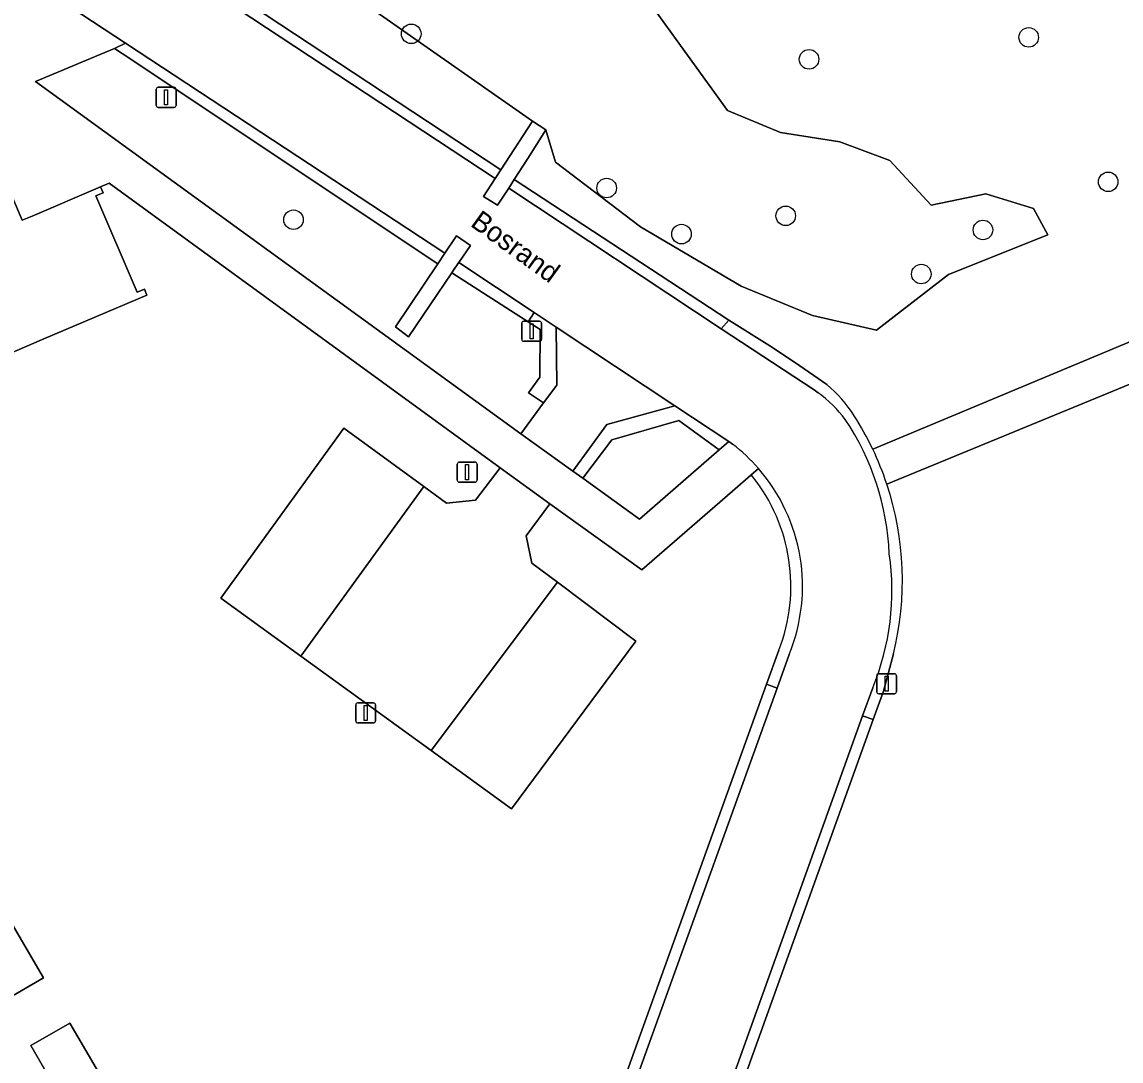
# Model space of a CAD drawing. Extents: x 156661 to 157576, y 383570 to 384425.
# Drawn here: x 156703.3 to 156758.2, y 383820 to 383871.9 of the extents above; entities that cross this region are included whole.
import ezdxf

# ---------------------------------------------------------------- set-up
doc = ezdxf.new("R2010")
doc.units = 0
for name, color, linetype in [('IMGEO_Boom', 7, 'Continuous'), ('IMGEO_Groenvoorziening', 7, 'Continuous'), ('IMGEO_Lichtmast', 7, 'Continuous'), ('IMGEO_Muur', 7, 'Continuous'), ('IMGEO_Openbare_ruimte_label', 7, 'Continuous'), ('IMGEO_Pand', 7, 'Continuous'), ('IMGEO_Parkeervlak_open', 7, 'Continuous'), ('IMGEO_Rijbaan_lokaal_gesloten', 7, 'Continuous'), ('IMGEO_Rijbaan_lokaal_halfverhard', 7, 'Continuous'), ('IMGEO_Rijbaan_lokaal_open', 7, 'Continuous'), ('IMGEO_Verkeersbordpaal', 7, 'Continuous'), ('IMGEO_Voetpad_halfverhard', 7, 'Continuous'), ('IMGEO_Voetpad_open', 7, 'Continuous')]:
    doc.layers.add(name, color=color, linetype=linetype)

msp = doc.modelspace()

# ---------------------------------------------------------------- linework, layer by layer
at = {"layer": 'IMGEO_Boom'}
for centre in [(156722.76, 383871.306), (156753.622, 383871.131), (156742.643, 383870.034), (156732.528, 383863.603), (156757.595, 383863.914), (156716.876, 383862.021), (156741.478, 383862.217), (156751.335, 383861.51), (156736.267, 383861.304), (156748.252, 383859.308)]:
    msp.add_circle(centre, 0.489, dxfattribs=at)
at = {"layer": 'IMGEO_Groenvoorziening'}
for points in [[(156716.183, 383876.493), (156711.792, 383874.695), (156713.985, 383873.248), (156727.234, 383864.506), (156728.814, 383866.945), (156719.836, 383873.239), (156729.567, 383879.935), (156725.091, 383891.83)], [(156729.567, 383879.935), (156738.568, 383867.47), (156741.218, 383866.376), (156744.176, 383865.917), (156746.68, 383864.987), (156748.744, 383862.749), (156751.487, 383863.31), (156753.862, 383862.586), (156754.58, 383861.26), (156749.606, 383859.293), (156746.013, 383856.5), (156742.821, 383857.242), (156739.254, 383858.704), (156734.225, 383861.669), (156729.97, 383864.893), (156729.492, 383866.507), (156728.58, 383865.086), (156727.906, 383864.035), (156738.637, 383857.007), (156740.683, 383855.728), (156741.967, 383854.876), (156743.528, 383853.784)], [(156739.821, 383849.196), (156739.736, 383849.264), (156738.813, 383848.462), (156734.285, 383844.531), (156729.684, 383847.837), (156728.506, 383846.223), (156728.792, 383844.873), (156730.073, 383843.909), (156733.979, 383840.969), (156727.773, 383832.588), (156723.749, 383835.507), (156717.245, 383840.225), (156713.248, 383843.125), (156719.396, 383851.612), (156723.39, 383848.696), (156724.521, 383847.87), (156725.971, 383848.018), (156727.201, 383849.634), (156707.654, 383863.85), (156707.237, 383863.666), (156707.363, 383863.372), (156706.995, 383863.214), (156709.056, 383858.397), (156709.424, 383858.554), (156709.549, 383858.26), (156704.398, 383856.067), (156692.389, 383850.886)], [(156745.823, 383850.568), (156763.462, 383857.925)], [(156764.227, 383856.088), (156746.53, 383848.809)], [(156740.523, 383838.828), (156741.132, 383840.518)], [(156746.863, 383840.339), (156746.357, 383838.464), (156745.849, 383837.052), (156732.467, 383799.845), (156731.117, 383796.092)], [(156725.657, 383797.552), (156727.175, 383801.768), (156740.523, 383838.828)], [(156696.966, 383836.824), (156704.38, 383824.151), (156702.342, 383822.975)]]:
    msp.add_lwpolyline(points, dxfattribs=at)
for points in [[(156738.568, 383867.47), (156729.567, 383879.935), (156719.836, 383873.239), (156728.814, 383866.945), (156729.492, 383866.507), (156729.97, 383864.893), (156734.225, 383861.669), (156739.254, 383858.704), (156742.821, 383857.242), (156746.013, 383856.5), (156749.606, 383859.293), (156754.58, 383861.26), (156753.862, 383862.586), (156751.487, 383863.31), (156748.744, 383862.749), (156746.68, 383864.987), (156744.176, 383865.917), (156741.218, 383866.376)], [(156708.317, 383870.317), (156707.93, 383870.575), (156707.439, 383870.369), (156703.983, 383868.92), (156728.241, 383851.334), (156729.371, 383852.868), (156728.621, 383853.376), (156729.181, 383854.15), (156729.2, 383856.537), (156728.602, 383856.921), (156724.79, 383859.373), (156722.627, 383856.175), (156721.975, 383856.663), (156724.088, 383859.825)], [(156738.154, 383850.528), (156736.128, 383851.996), (156732.78, 383851.024), (156731.338, 383849.106), (156734.161, 383847.065)], [(156696.966, 383836.824), (156695.097, 383835.702), (156699.159, 383829.422), (156702.342, 383822.975), (156704.38, 383824.151)], [(156705.701, 383821.894), (156703.75, 383820.772), (156715.859, 383799.798), (156781.035, 383689.82), (156782.468, 383690.79), (156717.547, 383800.885), (156717.868, 383801.092)], [(156782.468, 383690.79), (156781.035, 383689.82), (156715.859, 383799.798), (156703.75, 383820.772), (156705.701, 383821.894), (156717.868, 383801.092), (156717.547, 383800.885)]]:
    msp.add_lwpolyline(points, close=True, dxfattribs=at)
for centre, radius, start, end in [((156739.342, 383848.708), 6.579, 32.3261, 50.492), ((156731.863, 383843.898), 15.472, 25.5376, 32.5657), ((156732.931, 383843.717), 8.803, 338.6915, 38.4901), ((156732.053, 383843.998), 15.255, 346.1207, 18.3821)]:
    msp.add_arc(centre, radius, start, end, dxfattribs=at)
at = {"layer": 'IMGEO_Lichtmast'}
for p, q in [((156710.015, 383867.735), (156710.015, 383868.535)), ((156710.015, 383868.535), (156710.015, 383867.735)), ((156710.115, 383868.635), (156710.905, 383868.635)), ((156710.905, 383868.635), (156710.115, 383868.635)), ((156711.005, 383868.535), (156711.005, 383867.735)), ((156711.005, 383867.735), (156711.005, 383868.535)), ((156710.905, 383867.635), (156710.115, 383867.635)), ((156710.115, 383867.635), (156710.905, 383867.635)), ((156728.383, 383856.948), (156729.173, 383856.948)), ((156729.173, 383856.948), (156728.383, 383856.948)), ((156728.283, 383856.048), (156728.283, 383856.848)), ((156728.283, 383856.848), (156728.283, 383856.048)), ((156729.273, 383856.848), (156729.273, 383856.048)), ((156729.273, 383856.048), (156729.273, 383856.848)), ((156729.173, 383855.948), (156728.383, 383855.948)), ((156728.383, 383855.948), (156729.173, 383855.948)), ((156746.023, 383838.443), (156746.023, 383839.243)), ((156746.023, 383839.243), (156746.023, 383838.443)), ((156746.123, 383839.343), (156746.913, 383839.343)), ((156746.913, 383839.343), (156746.123, 383839.343)), ((156747.013, 383839.243), (156747.013, 383838.443)), ((156747.013, 383838.443), (156747.013, 383839.243)), ((156746.913, 383838.343), (156746.123, 383838.343)), ((156746.123, 383838.343), (156746.913, 383838.343)), ((156719.984, 383836.986), (156719.984, 383837.786)), ((156719.984, 383837.786), (156719.984, 383836.986)), ((156720.084, 383837.886), (156720.874, 383837.886)), ((156720.874, 383837.886), (156720.084, 383837.886)), ((156720.974, 383837.786), (156720.974, 383836.986)), ((156720.974, 383836.986), (156720.974, 383837.786)), ((156720.874, 383836.886), (156720.084, 383836.886)), ((156720.084, 383836.886), (156720.874, 383836.886))]:
    msp.add_line(p, q, dxfattribs=at)
for points in [[(156710.435, 383868.51), (156710.585, 383868.51), (156710.585, 383867.76), (156710.435, 383867.76), (156710.435, 383868.51)], [(156728.703, 383856.823), (156728.853, 383856.823), (156728.853, 383856.073), (156728.703, 383856.073), (156728.703, 383856.823)], [(156746.443, 383839.218), (156746.593, 383839.218), (156746.593, 383838.468), (156746.443, 383838.468), (156746.443, 383839.218)], [(156720.404, 383837.761), (156720.554, 383837.761), (156720.554, 383837.011), (156720.404, 383837.011), (156720.404, 383837.761)]]:
    msp.add_lwpolyline(points, dxfattribs=at)
for centre, start, end in [((156710.115, 383868.535), 90, 180), ((156710.115, 383868.535), 90, 180), ((156710.905, 383868.535), 0, 90), ((156710.905, 383868.535), 360, 90), ((156710.115, 383867.735), 180, 270), ((156710.115, 383867.735), 180, 270), ((156710.905, 383867.735), 270, 0), ((156710.905, 383867.735), 270, 0), ((156728.383, 383856.848), 90, 180), ((156728.383, 383856.848), 90, 180), ((156729.173, 383856.848), 0, 90), ((156729.173, 383856.848), 360, 90), ((156728.383, 383856.048), 180, 270), ((156728.383, 383856.048), 180, 270), ((156729.173, 383856.048), 270, 0), ((156729.173, 383856.048), 270, 0), ((156746.123, 383839.243), 90, 180), ((156746.123, 383839.243), 90, 180), ((156746.913, 383839.243), 0, 90), ((156746.913, 383839.243), 360, 90), ((156746.123, 383838.443), 180, 270), ((156746.123, 383838.443), 180, 270), ((156746.913, 383838.443), 270, 0), ((156746.913, 383838.443), 270, 0), ((156720.084, 383837.786), 90, 180), ((156720.084, 383837.786), 90, 180), ((156720.874, 383837.786), 0, 90), ((156720.874, 383837.786), 360, 90), ((156720.084, 383836.986), 180, 270), ((156720.084, 383836.986), 180, 270), ((156720.874, 383836.986), 270, 0), ((156720.874, 383836.986), 270, 0)]:
    msp.add_arc(centre, 0.1, start, end, dxfattribs=at)
at = {"layer": 'IMGEO_Muur'}
for points in [[(156728.58, 383865.086), (156729.492, 383866.507), (156728.814, 383866.945), (156727.234, 383864.506), (156726.961, 383864.085), (156726.376, 383863.181), (156727.078, 383862.744), (156727.631, 383863.606), (156727.906, 383864.035)], [(156724.79, 383859.373), (156724.843, 383859.451), (156725.129, 383859.874), (156725.135, 383859.882), (156725.714, 383860.739), (156725.016, 383861.213), (156724.436, 383860.345), (156724.088, 383859.825), (156721.975, 383856.663), (156722.627, 383856.175)]]:
    msp.add_lwpolyline(points, close=True, dxfattribs=at)
at = {"layer": 'IMGEO_Pand'}
msp.add_lwpolyline([(156691.257, 383860.885), (156691.614, 383860.059), (156692.177, 383858.875), (156689.45, 383857.699), (156689.54, 383857.489), (156692.389, 383850.886), (156704.398, 383856.067), (156709.549, 383858.26), (156709.424, 383858.554), (156709.056, 383858.397), (156706.995, 383863.214), (156707.363, 383863.372), (156707.237, 383863.666), (156703.808, 383862.199), (156703.32, 383861.991), (156700.923, 383867.6), (156697.694, 383866.219), (156697.33, 383866.987), (156697.143, 383866.907), (156697.403, 383866.292), (156692.428, 383864.216)], dxfattribs=at)
at = {"layer": 'IMGEO_Parkeervlak_open'}
for points in [[(156723.39, 383848.696), (156719.396, 383851.612), (156713.248, 383843.125), (156717.245, 383840.225)], [(156733.979, 383840.969), (156730.073, 383843.909), (156723.749, 383835.507), (156727.773, 383832.588)]]:
    msp.add_lwpolyline(points, close=True, dxfattribs=at)
at = {"layer": 'IMGEO_Rijbaan_lokaal_gesloten'}
for points in [[(156743.528, 383853.784), (156741.967, 383854.876), (156740.683, 383855.728), (156738.637, 383857.007), (156738.254, 383856.572), (156742.892, 383853.528), (156743.098, 383853.382)], [(156740.115, 383849.593), (156739.736, 383849.264), (156739.821, 383849.196)], [(156741.132, 383840.518), (156740.523, 383838.828), (156741.044, 383838.629), (156741.647, 383840.304)], [(156745.823, 383838.641), (156745.319, 383837.238), (156745.849, 383837.052), (156746.357, 383838.464), (156746.863, 383840.339)]]:
    msp.add_lwpolyline(points, dxfattribs=at)
msp.add_lwpolyline([(156729.996, 383856.661), (156730.03, 383853.762), (156729.371, 383852.868), (156728.241, 383851.334), (156730.84, 383849.466), (156732.536, 383851.791), (156735.934, 383852.726)], close=True, dxfattribs=at)
for centre, radius, start, end in [((156739.342, 383848.708), 6.579, 32.3261, 50.492), ((156739.015, 383847.873), 6.857, 37.4832, 53.4525), ((156733.573, 383844.771), 13.091, 2.4354, 33.7629), ((156731.863, 383843.898), 15.472, 25.5376, 32.5657), ((156732.205, 383844.073), 15.088, 18.2948, 25.4988), ((156733.345, 383843.706), 8.972, 337.7206, 41.0099), ((156732.931, 383843.717), 8.803, 338.6915, 38.4901), ((156732.053, 383843.998), 15.255, 346.1207, 18.3821), ((156734.2, 383843.477), 12.589, 337.4117, 8.4522)]:
    msp.add_arc(centre, radius, start, end, dxfattribs=at)
at = {"layer": 'IMGEO_Rijbaan_lokaal_halfverhard'}
for points in [[(156705.692, 383878.72), (156701.09, 383881.756), (156697.05, 383884.421), (156687.008, 383891.046), (156686.812, 383890.508), (156689.735, 383888.649), (156690.998, 383887.79), (156691.868, 383887.197), (156726.961, 383864.085), (156727.234, 383864.506), (156713.985, 383873.248), (156711.792, 383874.695), (156710.197, 383875.747), (156707.907, 383877.258), (156707.4, 383877.593)], [(156708.48, 383870.841), (156707.93, 383870.575), (156708.317, 383870.317), (156724.088, 383859.825), (156724.436, 383860.345)], [(156727.906, 383864.035), (156727.631, 383863.606), (156738.254, 383856.572), (156738.637, 383857.007)], [(156725.135, 383859.882), (156725.129, 383859.874), (156724.843, 383859.451), (156724.79, 383859.373), (156728.602, 383856.921), (156728.902, 383857.386)], [(156729.996, 383856.661), (156728.902, 383857.386), (156728.602, 383856.921), (156729.2, 383856.537), (156729.181, 383854.15), (156728.621, 383853.376), (156729.371, 383852.868), (156730.03, 383853.762)], [(156735.934, 383852.726), (156732.536, 383851.791), (156730.84, 383849.466), (156731.338, 383849.106), (156732.78, 383851.024), (156736.128, 383851.996), (156738.154, 383850.528), (156738.629, 383850.94)], [(156741.044, 383838.629), (156740.523, 383838.828), (156727.175, 383801.768), (156727.705, 383801.605)], [(156745.849, 383837.052), (156745.319, 383837.238), (156731.947, 383799.993), (156732.467, 383799.845)]]:
    msp.add_lwpolyline(points, close=True, dxfattribs=at)
at = {"layer": 'IMGEO_Rijbaan_lokaal_open'}
for points in [[(156743.098, 383853.382), (156742.892, 383853.528), (156738.254, 383856.572), (156727.631, 383863.606), (156727.078, 383862.744), (156726.376, 383863.181), (156726.961, 383864.085), (156691.868, 383887.197), (156689.389, 383883.375), (156703.099, 383874.38), (156703.578, 383874.065), (156708.48, 383870.841), (156724.436, 383860.345), (156725.016, 383861.213), (156725.714, 383860.739), (156725.135, 383859.882), (156728.902, 383857.386), (156729.996, 383856.661), (156735.934, 383852.726), (156738.629, 383850.94), (156738.819, 383850.814)], [(156741.647, 383840.304), (156741.044, 383838.629), (156727.705, 383801.605), (156726.169, 383797.342)], [(156745.319, 383837.238), (156745.823, 383838.641)], [(156730.604, 383796.251), (156731.947, 383799.993), (156745.319, 383837.238)]]:
    msp.add_lwpolyline(points, dxfattribs=at)
msp.add_lwpolyline([(156730.073, 383843.909), (156728.792, 383844.873), (156728.506, 383846.223), (156729.684, 383847.837), (156727.201, 383849.634), (156725.971, 383848.018), (156724.521, 383847.87), (156723.39, 383848.696), (156717.245, 383840.225), (156723.749, 383835.507)], close=True, dxfattribs=at)
for centre, radius, start, end in [((156739.015, 383847.873), 6.857, 37.4832, 53.4525), ((156733.573, 383844.771), 13.091, 2.4354, 33.7629), ((156733.338, 383843.698), 8.983, 41.0188, 52.3947), ((156733.345, 383843.706), 8.972, 337.7206, 41.0099), ((156734.2, 383843.477), 12.589, 337.4117, 8.4522)]:
    msp.add_arc(centre, radius, start, end, dxfattribs=at)
at = {"layer": 'IMGEO_Verkeersbordpaal'}
for p, q in [((156725.058, 383849.011), (156725.058, 383849.811)), ((156725.058, 383849.811), (156725.058, 383849.011)), ((156725.158, 383849.911), (156725.948, 383849.911)), ((156725.948, 383849.911), (156725.158, 383849.911)), ((156726.048, 383849.811), (156726.048, 383849.011)), ((156726.048, 383849.011), (156726.048, 383849.811)), ((156725.948, 383848.911), (156725.158, 383848.911)), ((156725.158, 383848.911), (156725.948, 383848.911))]:
    msp.add_line(p, q, dxfattribs=at)
msp.add_lwpolyline([(156725.478, 383849.786), (156725.628, 383849.786), (156725.628, 383849.036), (156725.478, 383849.036), (156725.478, 383849.786)], dxfattribs=at)
for centre, start, end in [((156725.158, 383849.811), 90, 180), ((156725.158, 383849.811), 90, 180), ((156725.948, 383849.811), 0, 90), ((156725.948, 383849.811), 360, 90), ((156725.158, 383849.011), 180, 270), ((156725.158, 383849.011), 180, 270), ((156725.948, 383849.011), 270, 0), ((156725.948, 383849.011), 270, 0)]:
    msp.add_arc(centre, 0.1, start, end, dxfattribs=at)
at = {"layer": 'IMGEO_Voetpad_halfverhard'}
for points in [[(156763.462, 383857.925), (156745.823, 383850.568)], [(156746.53, 383848.809), (156764.227, 383856.088)]]:
    msp.add_lwpolyline(points, dxfattribs=at)
msp.add_arc((156732.205, 383844.073), 15.088, 18.2948, 25.4988, dxfattribs=at)
at = {"layer": 'IMGEO_Voetpad_open'}
for points in [[(156738.819, 383850.814), (156738.629, 383850.94), (156738.154, 383850.528), (156734.161, 383847.065), (156731.338, 383849.106), (156730.84, 383849.466), (156728.241, 383851.334), (156703.983, 383868.92), (156707.439, 383870.369), (156707.93, 383870.575), (156708.48, 383870.841), (156703.578, 383874.065)], [(156697.403, 383866.292), (156697.143, 383866.907), (156697.33, 383866.987), (156697.694, 383866.219), (156700.923, 383867.6), (156703.32, 383861.991), (156703.808, 383862.199), (156707.237, 383863.666), (156707.654, 383863.85), (156727.201, 383849.634), (156729.684, 383847.837), (156734.285, 383844.531), (156738.813, 383848.462), (156739.736, 383849.264), (156740.115, 383849.593)]]:
    msp.add_lwpolyline(points, dxfattribs=at)
msp.add_arc((156733.338, 383843.698), 8.983, 41.0188, 52.3947, dxfattribs=at)

# ---------------------------------------------------------------- texts
at = {"layer": 'IMGEO_Openbare_ruimte_label'}
msp.add_text('Bosrand', height=1, rotation=324.0695, dxfattribs=at).set_placement((156725.667, 383861.74))

doc.saveas('drawing.dxf')
